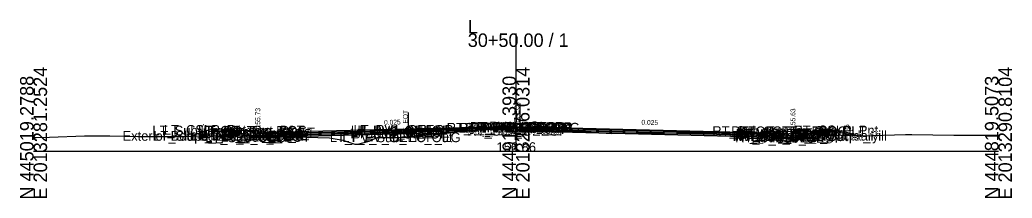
# Model space of a CAD drawing. Extents: x -26 to 4203, y -10 to 9526.
# Drawn here: x 1997.2 to 2202.8, y 490.3 to 527.2 of the extents above; entities that cross this region are included whole.
import ezdxf

# ---------------------------------------------------------------- set-up
doc = ezdxf.new("R2010")
doc.units = 0
for name, color, linetype in [('Default', 7, 'Continuous'), ('Exist CMT Pavement', 7, 'Continuous'), ('Exist Cross Section Cell', 7, 'Continuous'), ('Exist XS Center Line Elevation Label', 7, 'Continuous'), ('Exist XS Ground Line', 7, 'Continuous'), ('Prop CMT Conc Surface', 7, 'Continuous'), ('Prop CMT Concrete Structures', 7, 'Continuous'), ('Prop CMT Pvmt Course 1', 7, 'Continuous'), ('Prop CMT Pvmt Course 1 CG', 7, 'Continuous'), ('Prop CMT Pvmt Course 1 Wedge', 7, 'Continuous'), ('Prop CMT Pvmt Course 2', 7, 'Continuous'), ('Prop CMT Pvmt Course 2 Wedge', 7, 'Continuous'), ('Prop CMT Pvmt Course 3', 7, 'Continuous'), ('Prop CMT Pvmt Course 3 Wedge', 7, 'Continuous'), ('Prop CMT Pvmt Surface', 7, 'Continuous'), ('Prop CMT Pvmt Wedge Surface 1', 7, 'Continuous'), ('Prop CMT Pvmt Wedge Surface 2', 7, 'Continuous'), ('Prop CMT Pvmt Wedge Surface 3', 7, 'Continuous'), ('Prop CMT Slope Grass', 7, 'Continuous'), ('Prop CMT Subgrade Earthwork', 7, 'Continuous'), ('Prop XS Hydro Elevations', 7, 'Continuous'), ('Prop XS Label Text', 7, 'Continuous'), ('Prop XS SE Text', 7, 'Continuous'), ('Prop XS Side Slope Text', 7, 'Continuous'), ('Scratch_Level_0', 7, 'Continuous')]:
    doc.layers.add(name, color=color, linetype=linetype)

msp = doc.modelspace()

# ---------------------------------------------------------------- linework, layer by layer
at = {"layer": 'Exist CMT Pavement'}
for points in [[(2100, 504.86), (2099.6, 504.86), (2099.31, 504.84), (2098.27, 504.78), (2096.81, 504.69), (2095.5, 504.61), (2094.3, 504.54), (2093.1, 504.45), (2091.8, 504.35), (2089.99, 504.21), (2089.14, 504.15), (2089.09, 504.14), (2088.15, 504.05), (2086.83, 503.91), (2085.98, 503.83), (2084.33, 503.67), (2082.54, 503.5), (2081.83, 503.43), (2079.87, 503.22), (2079.32, 503.16), (2077.79, 503.01), (2077.66, 503), (2077.62, 502.99), (2077.06, 502.93), (2076.99, 502.93), (2076.45, 502.88)], [(2100, 504.86), (2100.76, 504.87)]]:
    msp.add_lwpolyline(points, dxfattribs=at)
at = {"layer": 'Exist Cross Section Cell'}
for p, q in [((2100, 500), (2100, 524.37)), ((2000, 500), (2100, 500)), ((2100, 500), (2200, 500))]:
    msp.add_line(p, q, dxfattribs=at)
at = {"layer": 'Exist XS Ground Line'}
msp.add_lwpolyline([(2000, 502.81), (2000.53, 502.82), (2003.28, 502.92), (2010.54, 503.22), (2015.81, 503.16), (2021.61, 503.07), (2024.49, 503.07), (2029.73, 503.07), (2035.83, 503.2), (2040.58, 503.19), (2045.8, 503.22), (2054.01, 502.99), (2061.35, 502.79), (2064.08, 502.26), (2066.57, 501.44), (2067.22, 501.48), (2069.53, 502.07), (2071.22, 502.83), (2075.62, 502.87), (2076.45, 502.88), (2077.06, 502.93), (2077.66, 503), (2079.32, 503.16), (2079.87, 503.22), (2081.83, 503.43), (2082.54, 503.5), (2084.33, 503.67), (2085.98, 503.83), (2086.83, 503.91), (2088.15, 504.05), (2089.09, 504.14), (2089.99, 504.21), (2091.8, 504.35), (2093.1, 504.45), (2094.3, 504.54), (2095.5, 504.61), (2096.81, 504.69), (2098.27, 504.78), (2099.6, 504.86), (2100, 504.86), (2100.76, 504.87), (2107.3, 504.48), (2119.7, 503.65), (2126.92, 503.77), (2134.81, 503.91), (2150.41, 503.72), (2150.91, 503.7), (2155.08, 503.66), (2161.01, 503.57), (2170.74, 503.17), (2171.53, 503.19), (2180.75, 503.43), (2182.04, 503.43), (2190.77, 503.32), (2192.56, 503.33), (2200, 503.31)], dxfattribs=at)
at = {"layer": 'Prop CMT Conc Surface'}
for points in [[(2041.99, 504.32), (2036.99, 504.42)], [(2046.49, 503.73), (2046.49, 504.23), (2045.99, 504.23)], [(2157.4, 503.63), (2157.4, 504.13), (2157.9, 504.13)], [(2161.9, 504.22), (2166.9, 504.32)], [(2048.49, 503.86), (2046.49, 503.73)], [(2155.4, 503.76), (2157.4, 503.63)]]:
    msp.add_lwpolyline(points, dxfattribs=at)
at = {"layer": 'Prop CMT Concrete Structures'}
for points in [[(2036.99, 504.09), (2036.99, 504.42)], [(2036.99, 504.42), (2041.99, 504.32)], [(2041.99, 503.99), (2036.99, 504.09)], [(2041.99, 504.32), (2041.99, 503.99)], [(2048.49, 503.86), (2046.49, 503.73), (2046.49, 504.23), (2045.99, 504.23)], [(2045.99, 504.23), (2045.99, 503.21), (2048.49, 503.28)], [(2155.4, 503.76), (2157.4, 503.63), (2157.4, 504.13), (2157.9, 504.13)], [(2157.9, 504.13), (2157.9, 503.12), (2155.4, 503.18)], [(2166.9, 504.32), (2161.9, 504.22)], [(2161.9, 504.22), (2161.9, 503.89)], [(2161.9, 503.89), (2166.9, 503.99)], [(2166.9, 503.99), (2166.9, 504.32)], [(2048.49, 503.28), (2048.49, 503.86)], [(2155.4, 503.18), (2155.4, 503.76)]]:
    msp.add_lwpolyline(points, dxfattribs=at)
at = {"layer": 'Prop CMT Pvmt Course 1'}
for points in [[(2100, 505.15), (2048.49, 503.86)], [(2048.49, 503.61), (2076.45, 504.31)], [(2077.66, 504.46), (2100, 505.02)], [(2077.66, 504.34), (2077.66, 504.46)], [(2100, 505.15), (2155.4, 503.76)], [(2100, 504.9), (2100, 505.15)], [(2100, 504.9), (2100, 505.15)], [(2100.76, 505), (2100, 505.02)], [(2100, 505.02), (2100, 504.9), (2100, 504.9)], [(2100, 505.02), (2100, 504.9), (2100, 504.9)], [(2100.76, 504.88), (2100.76, 505)], [(2155.4, 503.51), (2100.76, 504.88)], [(2048.49, 503.86), (2048.49, 503.61)], [(2155.4, 503.76), (2155.4, 503.51)]]:
    msp.add_lwpolyline(points, dxfattribs=at)
at = {"layer": 'Prop CMT Pvmt Course 1 CG'}
for points in [[(2048.49, 503.28), (2045.49, 503.2), (2045.15, 502.86)], [(2045.15, 502.86), (2048.49, 502.94)], [(2048.49, 502.94), (2048.49, 503.28)], [(2155.4, 503.18), (2158.4, 503.1), (2158.74, 502.76)], [(2155.4, 502.85), (2155.4, 503.18)], [(2158.74, 502.76), (2155.4, 502.85)]]:
    msp.add_lwpolyline(points, dxfattribs=at)
at = {"layer": 'Prop CMT Pvmt Course 1 Wedge'}
for points in [[(2077.66, 504.46), (2077.66, 504.46), (2077.79, 504.47), (2079.32, 504.51), (2079.87, 504.52), (2081.83, 504.57), (2082.54, 504.59), (2084.33, 504.63), (2085.98, 504.67), (2086.83, 504.69), (2088.15, 504.73), (2089.09, 504.75), (2089.14, 504.75), (2089.99, 504.77), (2091.8, 504.82), (2093.1, 504.85), (2094.3, 504.88), (2095.5, 504.91), (2096.81, 504.94), (2098.27, 504.98), (2099.31, 505.01), (2099.6, 505.01), (2100, 505.02)], [(2100, 504.9), (2099.6, 504.89), (2099.31, 504.88), (2098.27, 504.85), (2096.81, 504.82), (2095.5, 504.79), (2094.3, 504.76), (2093.1, 504.73), (2091.8, 504.69), (2089.99, 504.65), (2089.14, 504.63), (2089.09, 504.63), (2088.15, 504.6), (2086.83, 504.57), (2085.98, 504.55), (2084.33, 504.51), (2082.54, 504.46), (2081.83, 504.44), (2079.87, 504.39), (2079.32, 504.38), (2077.79, 504.34), (2077.66, 504.34), (2077.66, 504.34)], [(2077.66, 504.34), (2077.66, 504.46)], [(2100, 505.02), (2100, 504.9)], [(2100, 505.02), (2100.76, 505)], [(2100, 504.9), (2100, 505.02)], [(2100.76, 504.88), (2100, 504.9)], [(2100.76, 505), (2100.76, 504.88)]]:
    msp.add_lwpolyline(points, dxfattribs=at)
at = {"layer": 'Prop CMT Pvmt Course 2'}
for points in [[(2077.66, 504.34), (2048.49, 503.61)], [(2048.49, 503.28), (2076.45, 503.98)], [(2077.66, 504.01), (2077.66, 504.34)], [(2100.76, 504.54), (2100.76, 504.88)], [(2100.76, 504.88), (2155.4, 503.51)], [(2155.4, 503.18), (2100.76, 504.54)], [(2048.49, 503.61), (2048.49, 503.28)], [(2155.4, 503.51), (2155.4, 503.18)]]:
    msp.add_lwpolyline(points, dxfattribs=at)
at = {"layer": 'Prop CMT Pvmt Course 2 Wedge'}
for points in [[(2077.66, 504.34), (2077.66, 504.34), (2077.79, 504.34), (2079.32, 504.38), (2079.87, 504.39), (2081.83, 504.44), (2082.54, 504.46), (2084.33, 504.51), (2085.98, 504.55), (2086.83, 504.57), (2088.15, 504.6), (2089.09, 504.63), (2089.14, 504.63), (2089.99, 504.65), (2091.8, 504.69), (2093.1, 504.73), (2094.3, 504.76), (2095.5, 504.79), (2096.81, 504.82), (2098.27, 504.85), (2099.31, 504.88), (2099.6, 504.89), (2100, 504.9)], [(2100, 504.86), (2099.6, 504.86), (2099.31, 504.84), (2098.27, 504.78), (2096.81, 504.69), (2095.5, 504.61), (2094.3, 504.54), (2093.1, 504.45), (2091.94, 504.36), (2091.8, 504.36), (2089.99, 504.31), (2089.14, 504.29), (2089.09, 504.29), (2088.15, 504.27), (2086.83, 504.24), (2085.98, 504.21), (2084.33, 504.17), (2082.54, 504.13), (2081.83, 504.11), (2079.87, 504.06), (2079.32, 504.05), (2077.79, 504.01), (2077.66, 504.01), (2077.66, 504.01)], [(2077.66, 504.01), (2077.66, 504.34)], [(2100, 504.9), (2100.76, 504.88)], [(2100, 504.86), (2100, 504.9)], [(2100, 504.9), (2100, 504.86)], [(2100.76, 504.87), (2100, 504.86)], [(2100.76, 504.88), (2100.76, 504.87)]]:
    msp.add_lwpolyline(points, dxfattribs=at)
at = {"layer": 'Prop CMT Pvmt Course 3'}
for points in [[(2077.66, 504.01), (2048.49, 503.28)], [(2077.66, 503.67), (2077.66, 504.01)], [(2100.76, 504.54), (2155.4, 503.18)], [(2100.76, 504.21), (2100.76, 504.54)], [(2155.4, 502.85), (2100.76, 504.21)], [(2048.49, 502.94), (2077.66, 503.67)], [(2048.49, 503.28), (2048.49, 502.94)], [(2155.4, 503.18), (2155.4, 502.85)]]:
    msp.add_lwpolyline(points, dxfattribs=at)
at = {"layer": 'Prop CMT Pvmt Course 3 Wedge'}
for points in [[(2091.93, 504.36), (2091.8, 504.35), (2089.99, 504.21), (2089.14, 504.15), (2089.09, 504.14), (2088.15, 504.05), (2086.83, 503.91), (2085.98, 503.83), (2084.33, 503.67), (2082.54, 503.5), (2081.83, 503.43), (2079.87, 503.22), (2079.32, 503.16), (2077.79, 503.01), (2077.66, 503), (2077.62, 502.99), (2077.06, 502.93), (2076.99, 502.93), (2076.45, 502.88)], [(2077.66, 504.01), (2077.66, 504.01), (2077.79, 504.01), (2079.32, 504.05), (2079.87, 504.06), (2081.83, 504.11), (2082.54, 504.13), (2084.33, 504.17), (2085.98, 504.21), (2086.83, 504.24), (2088.15, 504.27), (2089.09, 504.29), (2089.14, 504.29), (2089.99, 504.31), (2091.8, 504.36), (2091.93, 504.36)]]:
    msp.add_lwpolyline(points, dxfattribs=at)
at = {"layer": 'Prop CMT Pvmt Surface'}
for points in [[(2100, 505.15), (2048.49, 503.86)], [(2100, 505.15), (2155.4, 503.76)]]:
    msp.add_lwpolyline(points, dxfattribs=at)
at = {"layer": 'Prop CMT Pvmt Wedge Surface 1'}
for points in [[(2076.45, 504.31), (2048.49, 503.61)], [(2100, 505.02), (2077.66, 504.46)], [(2077.66, 504.46), (2077.66, 504.34)], [(2100, 505.02), (2100.76, 505)], [(2100.76, 505), (2100.76, 504.88)], [(2100.76, 504.88), (2155.4, 503.51)], [(2048.49, 503.61), (2048.49, 503.86)], [(2155.4, 503.51), (2155.4, 503.76)]]:
    msp.add_lwpolyline(points, dxfattribs=at)
at = {"layer": 'Prop CMT Pvmt Wedge Surface 2'}
for points in [[(2100, 504.9), (2077.66, 504.34)], [(2100, 504.9), (2155.4, 503.51)], [(2048.49, 503.61), (2048.49, 503.86)], [(2155.4, 503.51), (2155.4, 503.76)]]:
    msp.add_lwpolyline(points, dxfattribs=at)
at = {"layer": 'Prop CMT Pvmt Wedge Surface 3'}
for points in [[(2100, 504.56), (2077.66, 504.01)], [(2100, 504.56), (2155.4, 503.18)], [(2048.49, 503.28), (2048.49, 503.86)], [(2155.4, 503.18), (2155.4, 503.76)]]:
    msp.add_lwpolyline(points, dxfattribs=at)
at = {"layer": 'Prop CMT Slope Grass'}
for points in [[(2045.99, 504.23), (2036.49, 504.42), (2032.63, 503.13)], [(2157.9, 504.13), (2167.4, 504.32), (2170.84, 503.18)]]:
    msp.add_lwpolyline(points, dxfattribs=at)
at = {"layer": 'Prop CMT Subgrade Earthwork'}
for points in [[(2048.49, 502.94), (2045.15, 502.86), (2043.73, 504.28)], [(2100.76, 504.21), (2100.75, 504.87)], [(2100.76, 504.21), (2155.4, 502.85)], [(2155.4, 502.85), (2158.74, 502.76), (2160.16, 504.18)], [(2077.66, 503.67), (2048.49, 502.94)], [(2077.66, 503.67), (2077.66, 503)]]:
    msp.add_lwpolyline(points, dxfattribs=at)
at = {"layer": 'Prop XS Label Text'}
for p, q in [((2100.76, 509.87), (2100.76, 504.87)), ((2077.66, 508), (2077.66, 503))]:
    msp.add_line(p, q, dxfattribs=at)

# ---------------------------------------------------------------- texts
at = {"layer": 'Default'}
msp.add_text('-', height=0.0001, dxfattribs=at).set_placement((2000, 500))
at = {"layer": 'Exist Cross Section Cell'}
for s, p in [('L', (2090, 524.37)), ('30+50.00 / 1', (2090, 521.57))]:
    msp.add_text(s, height=2.8, dxfattribs=at).set_placement(p)
for s, p in [('E 2013281.2524', (2002.8, 490)), ('E 2013286.0314', (2102.8, 490)), ('E 2013290.8104', (2202.8, 490)), ('N 445019.2788', (2000, 490)), ('N 444919.3930', (2100, 490)), ('N 444819.5073', (2200, 490))]:
    msp.add_text(s, height=2.8, rotation=90, dxfattribs=at).set_placement(p)
at = {"layer": 'Exist XS Center Line Elevation Label'}
msp.add_text('156.86', height=2, dxfattribs=at).set_placement((2095.97, 499.86))
at = {"layer": 'Prop XS Hydro Elevations'}
for s, p in [('155.73', (2046.99, 504.73)), ('155.63', (2157.9, 504.63))]:
    msp.add_text(s, height=1, rotation=90, dxfattribs=at).set_placement(p)
at = {"layer": 'Prop XS Label Text'}
for p in [(2100.66, 505.9), (2077.56, 504.02)]:
    msp.add_text('E. EOT', height=1, rotation=90, dxfattribs=at).set_placement(p)
at = {"layer": 'Prop XS SE Text'}
for rotation, p in [(1.4318, (2072.66, 505.46)), (358.5679, (2125.99, 505.5))]:
    msp.add_text('0.025', height=1, rotation=rotation, dxfattribs=at).set_placement(p)
at = {"layer": 'Prop XS Side Slope Text'}
for rotation, p in [(18.4349, (2034.08, 504.18)), (341.5651, (2168.16, 504.67))]:
    msp.add_text('3:1', height=1, rotation=rotation, dxfattribs=at).set_placement(p)
at = {"layer": 'Scratch_Level_0'}
for s, p in [('RT_PV_Sub_Tie_Out', (2085.65, 503.87)), ('RT_PV1_IEEOP', (2090.47, 504.02)), ('LT_PV1_IEEOP', (2090.52, 504.02)), ('RT_PV1_OEEOP', (2090.59, 504)), ('PV1_PGL', (2094.47, 504.15)), ('Exterior Boundary', (2018.45, 502.17)), ('LT_Sub_Trench_Out_DLT', (2024.64, 503.28)), ('LT_Slope_Fill', (2024.83, 502.17)), ('LT_CSLP_Pnt', (2027, 503.43)), ('LT_CG1_Shelf_Out', (2032.38, 502.21)), ('LT_CG_Top_Face', (2034.09, 503.24)), ('LT_CG_Top_BOC', (2034.61, 503.24)), ('LT_CG_Bot_BOC', (2034.64, 502.22)), ('LT_CG_Top_Gut', (2035.06, 502.74)), ('LT_Sub_OEOP', (2035.6, 501.87)), ('LT_CG_Bot_IE', (2038.74, 502.28)), ('LT_Sub_OEOT', (2038.91, 501.95)), ('LT_PV2_OEOT', (2039, 502.62)), ('LT_PV3_OEOT', (2039, 502.28)), ('LT_PV1_OEOT', (2039.57, 502.87)), ('LT_PV_Sub_Tie_Out', (2061.41, 501.88)), ('LT_Sub_OEEOP', (2065.66, 502.64)), ('LT_PV2_OEEOP', (2065.76, 503.31)), ('LT_PV3_OEEOP', (2065.76, 502.98)), ('LT_PV1_OEEOP', (2066.32, 503.43)), ('RT_PV_IEEOP_EG', (2088.14, 503.86)), ('LT_PV_IEEOP_EG', (2088.19, 503.86)), ('RT_PV_OEEOP_EG', (2088.26, 503.87)), ('RT_PV2_IEEOP', (2089.91, 503.9)), ('RT_PV3_IEEOP', (2089.91, 503.56)), ('RT_Sub_OEEOP', (2089.93, 503.21)), ('LT_PV2_IEEOP', (2089.95, 503.9)), ('LT_PV3_IEEOP', (2089.95, 503.56)), ('RT_PV2_OEEOP', (2090.02, 503.88)), ('RT_PV3_OEEOP', (2090.02, 503.54)), ('PV2_PGL', (2093.91, 503.9)), ('RT_Sub_Trench_Out_DLT', (2140.68, 503.18)), ('RT_CG_Top_Face', (2144.61, 503.13)), ('RT_CG1_Shelf_Out', (2144.9, 502.1)), ('RT_CG_Bot_IE', (2145.27, 502.18)), ('RT_Sub_OEOT', (2145.43, 501.85)), ('RT_PV2_OEOT', (2145.53, 502.51)), ('RT_PV3_OEOT', (2145.53, 502.18)), ('RT_CG_Top_Gut', (2145.59, 502.63)), ('RT_PV1_OEOT', (2146.09, 502.76)), ('RT_CG_Top_BOC', (2146.14, 503.13)), ('RT_CG_Bot_BOC', (2146.17, 502.12)), ('Exterior Boundary', (2153.75, 502.22)), ('RT_CSLP_Pnt', (2157.53, 503.32)), ('RT_Slope_Fill', (2160.08, 502.22)), ('LT_PV_OEEOP_EG', (2063.99, 501.88)), ('RT_Sub_OEOP', (2148.81, 501.76))]:
    msp.add_text(s, height=2, dxfattribs=at).set_placement(p)

doc.saveas('drawing.dxf')
